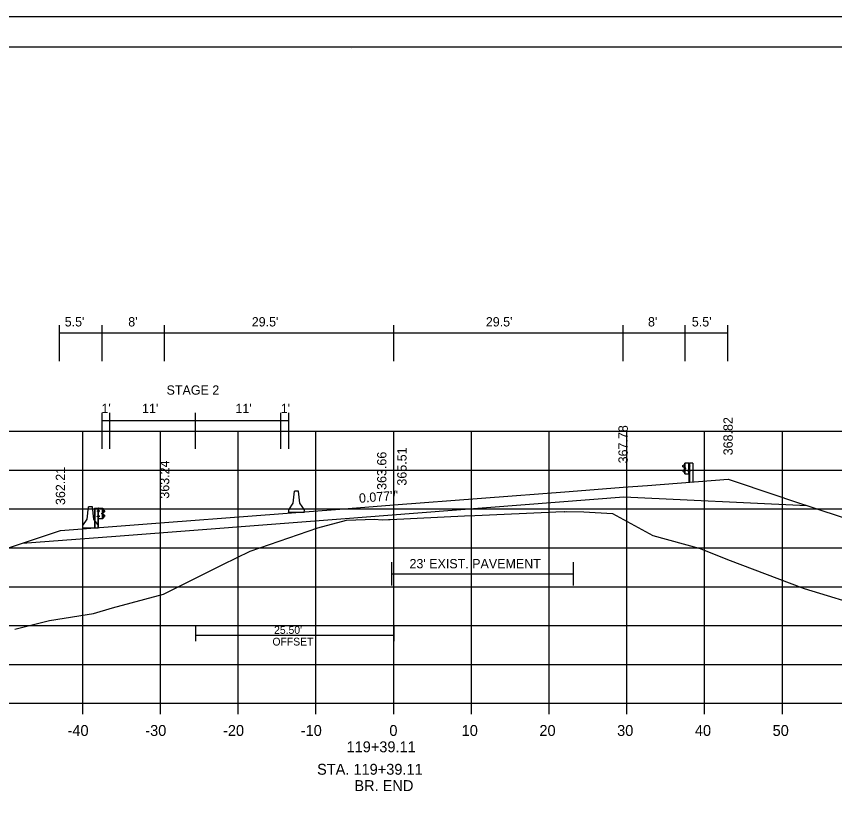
# Model space of a CAD drawing. Extents: x 1374859 to 1376773, y 382242 to 389804.
# Drawn here: x 1376086 to 1376191.3, y 384060.6 to 384161.8 of the extents above; entities that cross this region are included whole.
import ezdxf

# ---------------------------------------------------------------- set-up
doc = ezdxf.new("R2010")
doc.units = 0
for name, color, linetype in [('R_Axis', 7, 'Continuous'), ('R_Axis Annot', 7, 'Continuous'), ('R_Border', 7, 'Continuous'), ('R_Border Notes', 7, 'Continuous'), ('R_Draft', 7, 'Continuous'), ('R_Exist Surface', 7, 'Continuous'), ('R_Fin Surface', 7, 'Continuous'), ('R_Grid', 7, 'Continuous'), ('R_MOT', 7, 'Continuous'), ('R_No Plot', 7, 'Continuous'), ('R_Proposed Road', 7, 'Continuous'), ('R_Xsect Elev', 7, 'Continuous'), ('R_Xsect Slope', 7, 'Continuous')]:
    doc.layers.add(name, color=color, linetype=linetype)

msp = doc.modelspace()

# ---------------------------------------------------------------- linework, layer by layer
at = {"layer": 'R_Axis'}
for p, q in [((1375994.57, 384073.42), (1376274.57, 384073.42)), ((1376094.57, 384072.02), (1376094.57, 384073.42)), ((1376104.57, 384072.02), (1376104.57, 384073.42)), ((1376114.57, 384072.02), (1376114.57, 384073.42)), ((1376124.57, 384072.02), (1376124.57, 384073.42)), ((1376134.57, 384072.02), (1376134.57, 384073.42)), ((1376144.57, 384072.02), (1376144.57, 384073.42)), ((1376154.57, 384072.02), (1376154.57, 384073.42)), ((1376164.57, 384072.02), (1376164.57, 384073.42)), ((1376174.57, 384072.02), (1376174.57, 384073.42)), ((1376184.57, 384072.02), (1376184.57, 384073.42))]:
    msp.add_line(p, q, dxfattribs=at)
at = {"layer": 'R_Border'}
for p, q in [((1375976.57, 384157.88), (1376292.75, 384157.88)), ((1376129.09, 384157.62), (1376129.09, 384157.62)), ((1376129.09, 384157.62), (1376129.09, 384157.62))]:
    msp.add_line(p, q, dxfattribs=at)
at = {"layer": 'R_Border Notes'}
for points in [[(1376134.27, 384091.56), (1376134.27, 384088.56)], [(1376157.66, 384091.56), (1376157.66, 384088.56)], [(1376134.27, 384090.06), (1376157.66, 384090.06)]]:
    msp.add_lwpolyline(points, dxfattribs=at)
at = {"layer": 'R_Exist Surface'}
msp.add_lwpolyline([(1376085.84, 384082.94), (1376090.28, 384084.05), (1376095.93, 384084.95), (1376098.4, 384085.71), (1376104.95, 384087.45), (1376112.59, 384091.27), (1376116.12, 384092.97), (1376124.83, 384095.98), (1376128.5, 384096.99), (1376132.09, 384097.09), (1376133.08, 384097.02), (1376133.88, 384097.06), (1376134.12, 384097.07), (1376143.67, 384097.52), (1376145.02, 384097.59), (1376155.44, 384098.03), (1376156.55, 384098.07), (1376156.6, 384098.06), (1376156.77, 384098.07), (1376159.02, 384098.04), (1376162.72, 384097.83), (1376167.91, 384095.01), (1376173.98, 384093.33), (1376177.51, 384091.93), (1376187.39, 384088.18), (1376195.81, 384085.6)], dxfattribs=at)
at = {"layer": 'R_Fin Surface'}
for points in [[(1376053.59, 384082.95), (1376091.7, 384095.64), (1376098.94, 384096.19), (1376105.09, 384096.67), (1376127.65, 384098.4), (1376134.59, 384098.94), (1376157.15, 384100.67), (1376164.08, 384101.21), (1376167.2, 384101.45), (1376177.58, 384102.25), (1376183.85, 384100.16), (1376185.76, 384099.52), (1376192.14, 384097.4), (1376194.08, 384096.75), (1376215.8, 384089.5), (1376242.13, 384080.72), (1376244.25, 384080.02), (1376244.58, 384079.91)], [(1376086.81, 384094.01), (1376098.83, 384094.93), (1376128.31, 384097.2), (1376133.81, 384097.62), (1376164.16, 384099.96), (1376187.71, 384098.87)]]:
    msp.add_lwpolyline(points, dxfattribs=at)
at = {"layer": 'R_Grid'}
for p, q in [((1375994.57, 384108.42), (1376274.57, 384108.42)), ((1376094.57, 384073.42), (1376094.57, 384108.42)), ((1376104.57, 384073.42), (1376104.57, 384108.42)), ((1376114.57, 384073.42), (1376114.57, 384108.42)), ((1376124.57, 384073.42), (1376124.57, 384108.42)), ((1376134.57, 384073.42), (1376134.57, 384108.42)), ((1376144.57, 384073.42), (1376144.57, 384108.42)), ((1376154.57, 384073.42), (1376154.57, 384108.42)), ((1376164.57, 384073.42), (1376164.57, 384108.42)), ((1376174.57, 384073.42), (1376174.57, 384108.42)), ((1376184.57, 384073.42), (1376184.57, 384108.42)), ((1375994.57, 384103.42), (1376274.57, 384103.42)), ((1375994.57, 384098.42), (1376274.57, 384098.42)), ((1375994.57, 384093.42), (1376274.57, 384093.42)), ((1375994.57, 384088.42), (1376274.57, 384088.42)), ((1375994.57, 384083.42), (1376274.57, 384083.42)), ((1375994.57, 384078.42), (1376274.57, 384078.42)), ((1375994.57, 384073.42), (1376274.57, 384073.42))]:
    msp.add_line(p, q, dxfattribs=at)
at = {"layer": 'R_MOT'}
for p, q in [((1376091.57, 384117.41), (1376091.57, 384122.05)), ((1376097.07, 384117.41), (1376097.07, 384122.05)), ((1376105.07, 384117.41), (1376105.07, 384122.05)), ((1376134.57, 384117.41), (1376134.57, 384122.05)), ((1376164.07, 384117.41), (1376164.07, 384122.05)), ((1376172.07, 384117.41), (1376172.07, 384122.05)), ((1376177.57, 384117.41), (1376177.57, 384122.05)), ((1376091.57, 384121.05), (1376177.57, 384121.05)), ((1376097.07, 384106.15), (1376097.07, 384110.78)), ((1376097.07, 384109.78), (1376121.07, 384109.78)), ((1376098.07, 384106.15), (1376098.07, 384110.78)), ((1376109.07, 384106.15), (1376109.07, 384110.78)), ((1376120.07, 384106.15), (1376120.07, 384110.78)), ((1376121.07, 384106.15), (1376121.07, 384110.78)), ((1376121.65, 384099.14), (1376121.82, 384100.72)), ((1376122.07, 384100.72), (1376121.82, 384100.72)), ((1376122.32, 384100.72), (1376122.07, 384100.72)), ((1376122.49, 384099.14), (1376122.32, 384100.72)), ((1376095.15, 384097.11), (1376095.32, 384098.69)), ((1376095.57, 384098.69), (1376095.32, 384098.69)), ((1376095.82, 384098.69), (1376095.57, 384098.69)), ((1376095.99, 384097.11), (1376095.82, 384098.69)), ((1376121.07, 384097.97), (1376121.08, 384098.31)), ((1376121.08, 384098.31), (1376121.65, 384099.14)), ((1376123.08, 384098.31), (1376122.49, 384099.14)), ((1376123.07, 384097.97), (1376123.08, 384098.31)), ((1376123.07, 384097.97), (1376121.07, 384097.97)), ((1376094.57, 384095.94), (1376094.58, 384096.27)), ((1376094.58, 384096.27), (1376095.15, 384097.11)), ((1376096.58, 384096.27), (1376095.99, 384097.11)), ((1376096.57, 384095.94), (1376096.58, 384096.27)), ((1376096.57, 384095.94), (1376094.57, 384095.94)), ((1376109.07, 384083.31), (1376109.07, 384081.39)), ((1376134.57, 384083.31), (1376134.57, 384081.39)), ((1376134.57, 384082.13), (1376109.07, 384082.13))]:
    msp.add_line(p, q, dxfattribs=at)
at = {"layer": 'R_No Plot'}
msp.add_line((1375964.17, 384161.78), (1376297.5, 384161.78), dxfattribs=at)
for points in [[(1375964.16, 384161.78), (1376297.5, 384161.78), (1376297.5, 383948.44), (1375964.16, 383948.44)], [(1376210.49, 384157.88), (1376210.49, 384148), (1376246.22, 384148), (1376246.22, 384145.08), (1376269.42, 384145.08), (1376269.42, 384120.75), (1376292.75, 384120.75), (1376292.75, 383952.42), (1375976.57, 383952.42), (1375976.57, 384157.88)]]:
    msp.add_lwpolyline(points, close=True, dxfattribs=at)
at = {"layer": 'R_Proposed Road'}
for p, q in [((1376171.76, 384103.99), (1376171.89, 384104.1)), ((1376171.94, 384103.74), (1376171.77, 384103.85)), ((1376171.78, 384103.98), (1376171.91, 384104.08)), ((1376171.95, 384103.77), (1376171.78, 384103.87)), ((1376171.79, 384103.41), (1376171.94, 384103.51)), ((1376171.8, 384103.39), (1376171.96, 384103.49)), ((1376171.89, 384104.1), (1376172.01, 384104.16)), ((1376171.91, 384104.08), (1376172, 384104.13)), ((1376171.97, 384103.56), (1376171.97, 384103.7)), ((1376172, 384103.57), (1376172, 384103.7)), ((1376172.04, 384102.95), (1376172.04, 384104.31)), ((1376172.05, 384103.56), (1376172.05, 384103.69)), ((1376172.05, 384103.69), (1376172.1, 384103.69)), ((1376172.05, 384103.66), (1376172.1, 384103.66)), ((1376172.05, 384103.59), (1376172.09, 384103.59)), ((1376172.05, 384103.59), (1376172.1, 384103.59)), ((1376172.05, 384103.56), (1376172.1, 384103.56)), ((1376172.11, 384103.58), (1376172.11, 384103.67)), ((1376172.53, 384104.01), (1376172.48, 384104.01)), ((1376172.48, 384104.01), (1376172.48, 384103.88)), ((1376172.48, 384103.94), (1376172.54, 384103.94)), ((1376172.53, 384103.88), (1376172.48, 384103.88)), ((1376172.54, 384104.31), (1376172.54, 384104.31)), ((1376172.54, 384104.31), (1376172.61, 384104.31)), ((1376172.57, 384101.8), (1376172.57, 384104.31)), ((1376172.61, 384103.89), (1376172.61, 384104.01)), ((1376172.61, 384104.01), (1376172.65, 384104.01)), ((1376172.61, 384103.98), (1376172.66, 384103.98)), ((1376172.61, 384103.92), (1376172.65, 384103.92)), ((1376172.61, 384103.92), (1376172.66, 384103.92)), ((1376172.61, 384103.89), (1376172.66, 384103.89)), ((1376172.66, 384103.9), (1376172.66, 384104)), ((1376173.03, 384104.31), (1376173.03, 384101.8)), ((1376173.06, 384104.31), (1376173.06, 384101.8)), ((1376171.89, 384103.15), (1376171.76, 384103.26)), ((1376171.9, 384103.16), (1376171.78, 384103.27)), ((1376172, 384103.09), (1376171.89, 384103.15)), ((1376172.01, 384103.11), (1376171.9, 384103.16)), ((1376172.48, 384103.2), (1376172.48, 384103.32)), ((1376172.48, 384103.32), (1376172.53, 384103.32)), ((1376172.48, 384103.26), (1376172.54, 384103.26)), ((1376172.48, 384103.2), (1376172.53, 384103.2)), ((1376172.54, 384102.95), (1376172.57, 384102.95)), ((1376172.62, 384103.2), (1376172.62, 384103.32)), ((1376172.62, 384103.32), (1376172.67, 384103.32)), ((1376172.62, 384103.29), (1376172.67, 384103.29)), ((1376172.62, 384103.23), (1376172.66, 384103.23)), ((1376172.62, 384103.23), (1376172.67, 384103.23)), ((1376172.62, 384103.2), (1376172.67, 384103.2)), ((1376172.67, 384103.21), (1376172.67, 384103.31)), ((1376096.08, 384098.51), (1376096.08, 384096)), ((1376096.11, 384098.51), (1376096.11, 384096)), ((1376096.48, 384098.1), (1376096.48, 384098.19)), ((1376096.53, 384098.21), (1376096.49, 384098.21)), ((1376096.53, 384098.18), (1376096.49, 384098.18)), ((1376096.53, 384098.08), (1376096.53, 384098.21)), ((1376096.6, 384098.51), (1376096.54, 384098.51)), ((1376096.57, 384096), (1376096.57, 384098.51)), ((1376096.6, 384098.51), (1376096.6, 384098.51)), ((1376096.61, 384098.2), (1376096.66, 384098.2)), ((1376096.66, 384098.2), (1376096.66, 384098.08)), ((1376097.1, 384097.14), (1376097.1, 384098.5)), ((1376097.25, 384098.3), (1376097.14, 384098.36)), ((1376097.23, 384098.28), (1376097.14, 384098.33)), ((1376097.36, 384098.18), (1376097.23, 384098.28)), ((1376097.38, 384098.19), (1376097.25, 384098.3)), ((1376096.47, 384097.41), (1376096.47, 384097.51)), ((1376096.52, 384097.49), (1376096.47, 384097.49)), ((1376096.52, 384097.43), (1376096.47, 384097.43)), ((1376096.52, 384097.4), (1376096.47, 384097.4)), ((1376096.53, 384098.08), (1376096.48, 384098.08)), ((1376096.52, 384097.52), (1376096.48, 384097.52)), ((1376096.52, 384097.43), (1376096.48, 384097.43)), ((1376096.53, 384098.12), (1376096.49, 384098.12)), ((1376096.53, 384098.12), (1376096.49, 384098.12)), ((1376096.52, 384097.4), (1376096.52, 384097.52)), ((1376096.6, 384097.14), (1376096.57, 384097.14)), ((1376096.66, 384098.14), (1376096.6, 384098.14)), ((1376096.66, 384097.46), (1376096.6, 384097.46)), ((1376096.61, 384098.08), (1376096.66, 384098.08)), ((1376096.66, 384097.52), (1376096.61, 384097.52)), ((1376096.66, 384097.4), (1376096.61, 384097.4)), ((1376096.66, 384097.4), (1376096.66, 384097.52)), ((1376097.09, 384097.89), (1376097.04, 384097.89)), ((1376097.04, 384097.78), (1376097.04, 384097.87)), ((1376097.09, 384097.86), (1376097.04, 384097.86)), ((1376097.09, 384097.79), (1376097.04, 384097.79)), ((1376097.09, 384097.76), (1376097.04, 384097.76)), ((1376097.09, 384097.79), (1376097.05, 384097.79)), ((1376097.09, 384097.76), (1376097.09, 384097.89)), ((1376097.13, 384097.31), (1376097.24, 384097.36)), ((1376097.14, 384097.76), (1376097.14, 384097.9)), ((1376097.14, 384097.29), (1376097.25, 384097.35)), ((1376097.17, 384097.76), (1376097.17, 384097.9)), ((1376097.34, 384097.59), (1376097.18, 384097.69)), ((1376097.19, 384097.96), (1376097.36, 384098.07)), ((1376097.2, 384097.94), (1376097.37, 384098.05)), ((1376097.35, 384097.61), (1376097.2, 384097.71)), ((1376097.24, 384097.36), (1376097.37, 384097.47)), ((1376097.25, 384097.35), (1376097.38, 384097.45))]:
    msp.add_line(p, q, dxfattribs=at)
for points in [[(1376172.01, 384104.31), (1376172.01, 384102.95), (1376172.54, 384102.95), (1376172.54, 384104.31)], [(1376172.05, 384103.71), (1376172.05, 384103.54), (1376172.04, 384103.54), (1376172.04, 384103.71)], [(1376172.11, 384103.66), (1376172.11, 384103.6), (1376172.13, 384103.6), (1376172.13, 384103.66)], [(1376172.48, 384104.01), (1376172.48, 384103.88), (1376172.54, 384103.88), (1376172.54, 384104.01)], [(1376172.61, 384104.03), (1376172.61, 384103.86), (1376172.6, 384103.86), (1376172.6, 384104.03)], [(1376172.66, 384103.98), (1376172.66, 384103.92), (1376172.69, 384103.92), (1376172.69, 384103.98)], [(1376172.48, 384103.32), (1376172.48, 384103.2), (1376172.54, 384103.2), (1376172.54, 384103.32)], [(1376172.62, 384103.34), (1376172.62, 384103.17), (1376172.61, 384103.17), (1376172.61, 384103.34)], [(1376172.67, 384103.29), (1376172.67, 384103.23), (1376172.7, 384103.23), (1376172.7, 384103.29)], [(1376096.48, 384098.18), (1376096.48, 384098.12), (1376096.45, 384098.12), (1376096.45, 384098.18)], [(1376096.53, 384098.23), (1376096.53, 384098.06), (1376096.54, 384098.06), (1376096.54, 384098.23)], [(1376097.13, 384098.51), (1376097.13, 384097.14), (1376096.6, 384097.14), (1376096.6, 384098.51)], [(1376096.66, 384098.2), (1376096.66, 384098.08), (1376096.6, 384098.08), (1376096.6, 384098.2)], [(1376096.47, 384097.49), (1376096.47, 384097.43), (1376096.44, 384097.43), (1376096.44, 384097.49)], [(1376096.52, 384097.54), (1376096.52, 384097.37), (1376096.53, 384097.37), (1376096.53, 384097.54)], [(1376096.66, 384097.52), (1376096.66, 384097.4), (1376096.6, 384097.4), (1376096.6, 384097.52)], [(1376097.03, 384097.86), (1376097.03, 384097.79), (1376097.01, 384097.79), (1376097.01, 384097.86)], [(1376097.09, 384097.91), (1376097.09, 384097.74), (1376097.1, 384097.74), (1376097.1, 384097.91)]]:
    msp.add_lwpolyline(points, close=True, dxfattribs=at)
for points in [[(1376173.06, 384104.31), (1376172.61, 384104.31), (1376172.61, 384101.8)], [(1376096.08, 384098.51), (1376096.54, 384098.51), (1376096.53, 384096)]]:
    msp.add_lwpolyline(points, dxfattribs=at)
for centre, radius, start, end in [((1376171.81, 384103.92), 0.0856, 122.0217, 240.7501), ((1376171.81, 384103.92), 0.062, 122.0217, 240.7501), ((1376171.98, 384103.62), 0.0453, 93.9303, 257.0446), ((1376171.91, 384103.69), 0.0622, 4.9556, 61.894), ((1376171.91, 384103.69), 0.0865, 4.9556, 61.894), ((1376171.93, 384103.55), 0.0462, 293.1464, 8.2196), ((1376171.93, 384103.55), 0.0703, 293.1464, 8.2196), ((1376172.08, 384103.67), 0.022, 317.7756, 45.4255), ((1376172.01, 384103.63), 0.0922, 339.7423, 20.2577), ((1376172.08, 384103.58), 0.025, 323.3766, 39.0666), ((1376172.64, 384103.99), 0.022, 317.7756, 45.4255), ((1376172.57, 384103.95), 0.0922, 339.7423, 20.2577), ((1376172.64, 384103.9), 0.025, 323.3766, 39.0666), ((1376171.85, 384103.32), 0.109, 120.88, 214.7816), ((1376171.85, 384103.32), 0.0854, 120.88, 214.7816), ((1376172.65, 384103.31), 0.022, 317.7756, 45.4255), ((1376172.58, 384103.26), 0.0922, 339.7423, 20.2577), ((1376172.65, 384103.21), 0.025, 323.3766, 39.0666), ((1376096.5, 384098.19), 0.022, 134.5745, 222.2244), ((1376096.57, 384098.15), 0.0922, 159.7423, 200.2577), ((1376097.33, 384098.12), 0.062, 299.2499, 57.9783), ((1376097.33, 384098.12), 0.0856, 299.2499, 57.9783), ((1376096.49, 384097.5), 0.022, 134.5745, 222.2244), ((1376096.56, 384097.46), 0.0922, 159.7423, 200.2577), ((1376096.49, 384097.41), 0.025, 140.9334, 216.6234), ((1376096.5, 384098.1), 0.025, 140.9334, 216.6234), ((1376097.06, 384097.87), 0.022, 134.5745, 222.2244), ((1376097.13, 384097.83), 0.0922, 159.7423, 200.2577), ((1376097.06, 384097.78), 0.025, 140.9334, 216.6234), ((1376097.23, 384097.89), 0.0865, 118.106, 175.0444), ((1376097.21, 384097.75), 0.0703, 171.7804, 246.8536), ((1376097.16, 384097.82), 0.0453, 282.9554, 86.0697), ((1376097.23, 384097.89), 0.0622, 118.106, 175.0444), ((1376097.21, 384097.75), 0.0462, 171.7804, 246.8536), ((1376097.3, 384097.52), 0.0854, 325.2184, 59.12), ((1376097.3, 384097.52), 0.109, 325.2184, 59.12)]:
    msp.add_arc(centre, radius, start, end, dxfattribs=at)

# ---------------------------------------------------------------- texts
at = {"layer": 'R_Axis Annot'}
for s, p in [('-40', (1376092.61, 384069.22)), ('-30', (1376102.61, 384069.22)), ('-20', (1376112.61, 384069.22)), ('-10', (1376122.61, 384069.22)), ('0', (1376134.01, 384069.22)), ('10', (1376143.31, 384069.22)), ('20', (1376153.31, 384069.22)), ('30', (1376163.31, 384069.22)), ('40', (1376173.31, 384069.22)), ('50', (1376183.31, 384069.22)), ('119+39.11', (1376128.5, 384067.12))]:
    msp.add_text(s, height=1.4, dxfattribs=at).set_placement(p)
at = {"layer": 'R_Border Notes'}
msp.add_text("23' EXIST. PAVEMENT", height=1.2, rotation=0, dxfattribs=at).set_placement((1376136.6, 384090.78))
for s, p in [('STA. 119+39.11', (1376124.71, 384064.23)), ('BR. END', (1376129.51, 384062.13))]:
    msp.add_text(s, height=1.4, dxfattribs=at).set_placement(p)
at = {"layer": 'R_Draft'}
for s, p in [("25.50'", (1376119.18, 384082.35)), ('OFFSET', (1376118.97, 384080.85))]:
    msp.add_text(s, height=1, dxfattribs=at).set_placement(p)
at = {"layer": 'R_MOT'}
for s, p in [("5.5'", (1376092.25, 384121.89)), ("8'", (1376100.42, 384121.89)), ("29.5'", (1376116.31, 384121.89)), ("29.5'", (1376146.42, 384121.89)), ("8'", (1376167.28, 384121.89)), ("5.5'", (1376172.92, 384121.89)), ("1'", (1376096.98, 384110.74)), ("11'", (1376102.19, 384110.74)), ("11'", (1376114.2, 384110.74)), ("1'", (1376120.04, 384110.74))]:
    msp.add_text(s, height=1.2, dxfattribs=at).set_placement(p)
msp.add_text('STAGE 2', height=1.2, rotation=0, dxfattribs=at).set_placement((1376105.35, 384113.11))
at = {"layer": 'R_Xsect Elev'}
for s, p in [('368.82', (1376178.18, 384105.32)), ('367.78', (1376164.68, 384104.28)), ('363.66', (1376133.63, 384100.87)), ('365.51', (1376136.22, 384101.42)), ('363.24', (1376105.69, 384099.74)), ('363.24', (1376105.69, 384099.74)), ('362.21', (1376092.3, 384098.92))]:
    msp.add_text(s, height=1.2, rotation=90, dxfattribs=at).set_placement(p)
at = {"layer": 'R_Xsect Slope'}
msp.add_text("0.077'/'", height=1.2, rotation=4.4031, dxfattribs=at).set_placement((1376130.15, 384099.2))

doc.saveas('drawing.dxf')
